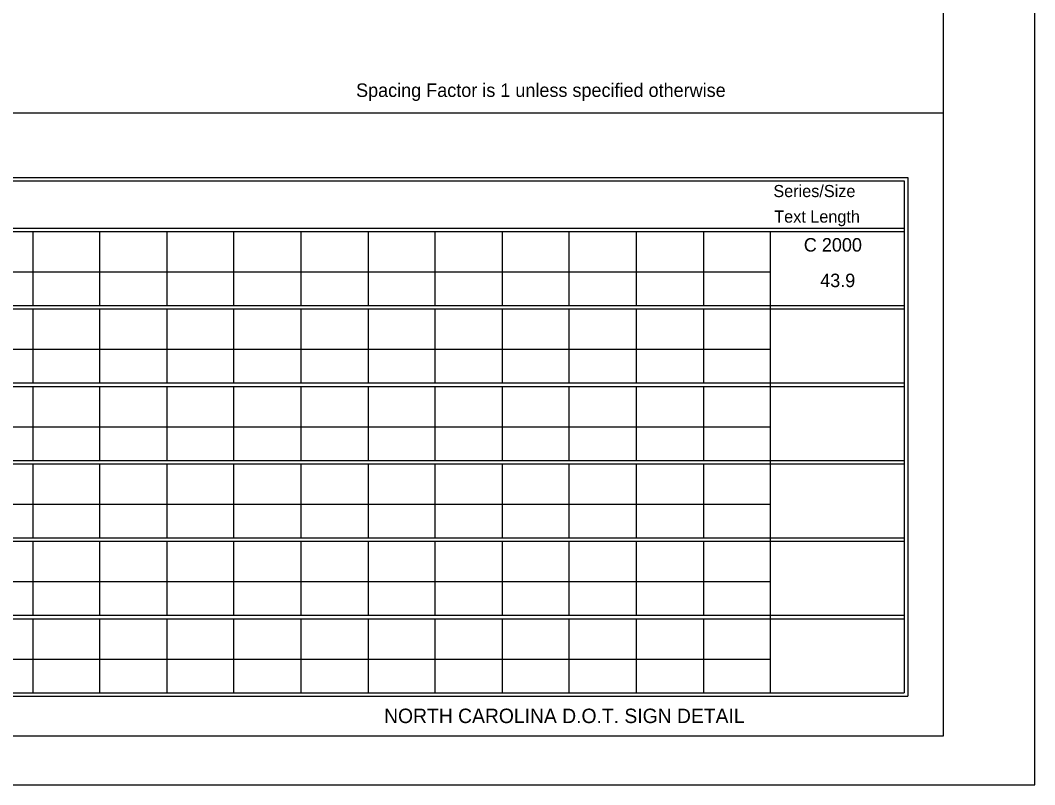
# Model space of a CAD drawing. Extents: x 1788.1 to 1851.2, y 237.2 to 283.4.
# Drawn here: x 1804.44 to 1818.27, y 237.17 to 247.6 of the extents above; entities that cross this region are included whole.
import ezdxf

# ---------------------------------------------------------------- set-up
doc = ezdxf.new("R2010")
doc.units = 0
doc.layers.add('Old_Level_2', color=7, linetype='Continuous')
doc.layers.add('Sheet Plot Border Outside CELL', color=7, linetype='Continuous')

msp = doc.modelspace()

# ---------------------------------------------------------------- linework, layer by layer
at = {"layer": 'Old_Level_2'}
for p, q in [((1799.855, 246.338), (1817.019, 246.338)), ((1789.056, 244.765), (1810.834, 244.765)), ((1789.056, 244.719), (1810.834, 244.719)), ((1804.61, 244.719), (1804.61, 243.709)), ((1805.519, 244.719), (1805.519, 243.709)), ((1806.437, 244.719), (1806.437, 243.709)), ((1807.346, 244.719), (1807.346, 243.709)), ((1808.265, 244.719), (1808.265, 243.709)), ((1809.183, 244.719), (1809.183, 243.709)), ((1809.859, 244.765), (1816.491, 244.765)), ((1809.859, 244.719), (1816.491, 244.719)), ((1810.092, 244.719), (1810.092, 243.709)), ((1810.092, 244.719), (1810.092, 243.709)), ((1811.01, 244.719), (1811.01, 243.709)), ((1811.919, 244.719), (1811.919, 243.709)), ((1812.837, 244.719), (1812.837, 243.709)), ((1813.755, 244.719), (1813.755, 243.709)), ((1814.664, 244.719), (1814.664, 238.595)), ((1789.974, 244.168), (1810.834, 244.168)), ((1809.859, 244.168), (1814.664, 244.168)), ((1814.664, 243.959), (1814.664, 243.709)), ((1789.056, 243.709), (1810.834, 243.709)), ((1809.859, 243.709), (1816.491, 243.709)), ((1789.056, 243.663), (1810.834, 243.663)), ((1804.61, 243.663), (1804.61, 242.652)), ((1805.519, 243.663), (1805.519, 242.652)), ((1806.437, 243.663), (1806.437, 242.652)), ((1807.346, 243.663), (1807.346, 242.652)), ((1808.265, 243.663), (1808.265, 242.652)), ((1809.183, 243.663), (1809.183, 242.652)), ((1809.859, 243.663), (1816.491, 243.663)), ((1810.092, 243.663), (1810.092, 242.652)), ((1810.092, 243.663), (1810.092, 242.652)), ((1811.01, 243.663), (1811.01, 242.652)), ((1811.919, 243.663), (1811.919, 242.652)), ((1812.837, 243.663), (1812.837, 242.652)), ((1813.755, 243.663), (1813.755, 242.652)), ((1814.664, 243.663), (1814.664, 243.183)), ((1789.974, 243.112), (1810.834, 243.112)), ((1809.859, 243.112), (1814.664, 243.112)), ((1814.664, 242.981), (1814.664, 242.652)), ((1789.056, 242.652), (1810.834, 242.652)), ((1789.056, 242.606), (1810.834, 242.606)), ((1804.61, 242.606), (1804.61, 241.596)), ((1805.519, 242.606), (1805.519, 241.596)), ((1806.437, 242.606), (1806.437, 241.596)), ((1807.346, 242.606), (1807.346, 241.596)), ((1808.265, 242.606), (1808.265, 241.596)), ((1809.183, 242.606), (1809.183, 241.596)), ((1809.859, 242.652), (1816.491, 242.652)), ((1809.859, 242.606), (1816.491, 242.606)), ((1810.092, 242.606), (1810.092, 241.596)), ((1810.092, 242.606), (1810.092, 241.596)), ((1811.01, 242.606), (1811.01, 241.596)), ((1811.919, 242.606), (1811.919, 241.596)), ((1812.837, 242.606), (1812.837, 241.596)), ((1813.755, 242.606), (1813.755, 241.596)), ((1814.664, 242.606), (1814.664, 242.196)), ((1789.974, 242.055), (1810.834, 242.055)), ((1809.859, 242.055), (1814.664, 242.055)), ((1814.664, 241.894), (1814.664, 241.596)), ((1789.056, 241.596), (1810.834, 241.596)), ((1789.056, 241.55), (1810.834, 241.55)), ((1804.61, 241.55), (1804.61, 240.54)), ((1805.519, 241.55), (1805.519, 240.54)), ((1806.437, 241.55), (1806.437, 240.54)), ((1807.346, 241.55), (1807.346, 240.54)), ((1808.265, 241.55), (1808.265, 240.54)), ((1809.183, 241.55), (1809.183, 240.54)), ((1809.859, 241.596), (1816.491, 241.596)), ((1809.859, 241.55), (1816.491, 241.55)), ((1810.092, 241.55), (1810.092, 240.54)), ((1810.092, 241.55), (1810.092, 240.54)), ((1811.01, 241.55), (1811.01, 240.54)), ((1811.919, 241.55), (1811.919, 240.54)), ((1812.837, 241.55), (1812.837, 240.54)), ((1813.755, 241.55), (1813.755, 240.54)), ((1814.664, 241.55), (1814.664, 241.107)), ((1789.974, 240.999), (1810.834, 240.999)), ((1809.859, 240.999), (1814.664, 240.999)), ((1814.664, 240.805), (1814.664, 240.54)), ((1804.61, 240.657), (1804.61, 240.54)), ((1805.519, 240.657), (1805.519, 240.54)), ((1806.437, 240.657), (1806.437, 240.54)), ((1807.346, 240.657), (1807.346, 240.54)), ((1808.265, 240.657), (1808.265, 240.54)), ((1809.183, 240.657), (1809.183, 240.54)), ((1810.092, 240.657), (1810.092, 240.54)), ((1810.092, 240.657), (1810.092, 240.54)), ((1811.01, 240.657), (1811.01, 240.54)), ((1811.919, 240.657), (1811.919, 240.54)), ((1812.837, 240.657), (1812.837, 240.54)), ((1813.755, 240.657), (1813.755, 240.54)), ((1814.664, 240.657), (1814.664, 240.54)), ((1789.056, 240.54), (1810.834, 240.54)), ((1789.056, 240.54), (1810.834, 240.54)), ((1789.056, 240.494), (1810.834, 240.494)), ((1789.056, 240.494), (1810.834, 240.494)), ((1804.61, 240.494), (1804.61, 239.549)), ((1804.61, 240.494), (1804.61, 239.483)), ((1805.519, 240.494), (1805.519, 239.549)), ((1805.519, 240.494), (1805.519, 239.483)), ((1806.437, 240.494), (1806.437, 239.549)), ((1806.437, 240.494), (1806.437, 239.483)), ((1807.346, 240.494), (1807.346, 239.549)), ((1807.346, 240.494), (1807.346, 239.483)), ((1808.265, 240.494), (1808.265, 239.549)), ((1808.265, 240.494), (1808.265, 239.483)), ((1809.183, 240.494), (1809.183, 239.549)), ((1809.183, 240.494), (1809.183, 239.483)), ((1809.859, 240.54), (1816.491, 240.54)), ((1809.859, 240.54), (1816.491, 240.54)), ((1809.859, 240.494), (1816.491, 240.494)), ((1809.859, 240.494), (1816.491, 240.494)), ((1810.092, 240.494), (1810.092, 239.549)), ((1810.092, 240.494), (1810.092, 239.483)), ((1810.092, 240.494), (1810.092, 239.549)), ((1810.092, 240.494), (1810.092, 239.483)), ((1811.01, 240.494), (1811.01, 239.549)), ((1811.01, 240.494), (1811.01, 239.483)), ((1811.919, 240.494), (1811.919, 239.549)), ((1811.919, 240.494), (1811.919, 239.483)), ((1812.837, 240.494), (1812.837, 239.549)), ((1812.837, 240.494), (1812.837, 239.483)), ((1813.755, 240.494), (1813.755, 239.549)), ((1813.755, 240.494), (1813.755, 239.483)), ((1814.664, 240.494), (1814.664, 240.039)), ((1814.664, 240.494), (1814.664, 240.039)), ((1789.974, 239.942), (1810.834, 239.942)), ((1789.974, 239.942), (1810.834, 239.942)), ((1809.859, 239.942), (1814.664, 239.942)), ((1809.859, 239.942), (1814.426, 239.942)), ((1814.664, 239.777), (1814.664, 239.549)), ((1814.664, 239.777), (1814.664, 239.483)), ((1804.61, 239.601), (1804.61, 239.483)), ((1805.519, 239.601), (1805.519, 239.483)), ((1806.437, 239.601), (1806.437, 239.483)), ((1807.346, 239.601), (1807.346, 239.483)), ((1808.265, 239.601), (1808.265, 239.483)), ((1809.183, 239.601), (1809.183, 239.483)), ((1810.092, 239.601), (1810.092, 239.483)), ((1810.092, 239.601), (1810.092, 239.483)), ((1811.01, 239.601), (1811.01, 239.483)), ((1811.919, 239.601), (1811.919, 239.483)), ((1812.837, 239.601), (1812.837, 239.483)), ((1813.755, 239.601), (1813.755, 239.483)), ((1814.664, 239.601), (1814.664, 239.483)), ((1789.056, 239.483), (1810.834, 239.483)), ((1789.056, 239.483), (1810.834, 239.483)), ((1789.056, 239.437), (1810.834, 239.437)), ((1789.056, 239.437), (1810.834, 239.437)), ((1804.61, 239.437), (1804.61, 238.427)), ((1804.61, 239.437), (1804.61, 238.427)), ((1805.519, 239.437), (1805.519, 238.427)), ((1805.519, 239.437), (1805.519, 238.427)), ((1806.437, 239.437), (1806.437, 238.427)), ((1806.437, 239.437), (1806.437, 238.427)), ((1807.346, 239.437), (1807.346, 238.427)), ((1807.346, 239.437), (1807.346, 238.427)), ((1808.265, 239.437), (1808.265, 238.427)), ((1808.265, 239.437), (1808.265, 238.427)), ((1809.183, 239.437), (1809.183, 238.427)), ((1809.183, 239.437), (1809.183, 238.427)), ((1809.859, 239.483), (1816.491, 239.483)), ((1809.859, 239.483), (1816.491, 239.483)), ((1809.859, 239.437), (1816.491, 239.437)), ((1809.859, 239.437), (1816.491, 239.437)), ((1810.092, 239.437), (1810.092, 238.427)), ((1810.092, 239.437), (1810.092, 238.427)), ((1810.092, 239.437), (1810.092, 238.427)), ((1810.092, 239.437), (1810.092, 238.427)), ((1811.01, 239.437), (1811.01, 238.427)), ((1811.01, 239.437), (1811.01, 238.427)), ((1811.919, 239.437), (1811.919, 238.427)), ((1811.919, 239.437), (1811.919, 238.427)), ((1812.837, 239.437), (1812.837, 238.427)), ((1812.837, 239.437), (1812.837, 238.427)), ((1813.755, 239.437), (1813.755, 238.427)), ((1813.755, 239.437), (1813.755, 238.427)), ((1814.664, 239.437), (1814.664, 239.012)), ((1814.664, 239.437), (1814.664, 239.012)), ((1789.974, 238.886), (1810.834, 238.886)), ((1789.974, 238.886), (1810.834, 238.886)), ((1809.859, 238.886), (1814.664, 238.886)), ((1809.859, 238.886), (1814.488, 238.886)), ((1814.664, 238.689), (1814.664, 238.427)), ((1814.664, 238.689), (1814.664, 238.427)), ((1789.056, 238.427), (1810.834, 238.427)), ((1789.056, 238.427), (1810.834, 238.427)), ((1809.859, 238.427), (1816.491, 238.427)), ((1809.859, 238.427), (1816.491, 238.427)), ((1789.009, 238.381), (1810.834, 238.381)), ((1789.056, 238.381), (1810.834, 238.381)), ((1809.859, 238.381), (1816.538, 238.381)), ((1809.859, 238.381), (1816.491, 238.381))]:
    msp.add_line(p, q, dxfattribs=at)
msp.add_lwpolyline([(1788.693, 257.479), (1817.019, 257.479), (1817.019, 237.834), (1788.693, 237.834)], close=True, dxfattribs=at)
for points in [[(1789.009, 239.549), (1789.009, 245.454), (1810.834, 245.454)], [(1789.056, 239.549), (1789.056, 245.408), (1810.834, 245.408)], [(1809.859, 245.454), (1816.538, 245.454), (1816.538, 239.549)], [(1809.859, 245.408), (1816.491, 245.408), (1816.491, 239.549)], [(1816.491, 240.657), (1816.491, 238.427)], [(1816.538, 240.657), (1816.538, 238.381)]]:
    msp.add_lwpolyline(points, dxfattribs=at)
at = {"layer": 'Sheet Plot Border Outside CELL'}
msp.add_lwpolyline([(1818.269, 258.025), (1788.097, 258.025), (1788.097, 237.172), (1818.269, 237.172)], close=True, dxfattribs=at)

# ---------------------------------------------------------------- texts
at = {"layer": 'Old_Level_2'}
for s, height, p in [('Spacing Factor is 1 unless specified otherwise', 0.18373, (1809.017, 246.553)), ('Series/Size', 0.16535, (1814.706, 245.187)), ('Text Length', 0.16535, (1814.718, 244.839)), ('NORTH CAROLINA D.O.T. SIGN DETAIL', 0.19685, (1809.399, 238.013))]:
    msp.add_text(s, height=height, rotation=360, dxfattribs=at).set_placement(p)
for s, p in [('C 2000', (1815.121, 244.444)), ('43.9', (1815.344, 243.959))]:
    msp.add_text(s, height=0.1837, dxfattribs=at).set_placement(p)

doc.saveas('drawing.dxf')
